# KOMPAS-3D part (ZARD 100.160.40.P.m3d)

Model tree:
1. Операция без истории:1
2. Операция без истории:2
3. Операция без истории:3
4. Операция без истории:4
5. Операция без истории:5
6. Операция без истории:6
7. Операция без истории:7
8. Операция без истории:8
9. Операция без истории:9
10. Операция без истории:10
11. Операция без истории:11
12. Операция без истории:12
13. Операция без истории:13
14. Операция без истории:14
15. Операция без истории:15
16. Операция без истории:16
17. Операция без истории:17
18. Операция без истории:18
19. Операция без истории:19
20. Операция без истории:20
21. Операция без истории:21
22. Операция без истории:22
23. Операция без истории:23
24. Операция без истории:24
25. Операция без истории:25
26. Операция без истории:26
27. Операция без истории:27
28. Операция без истории:28
29. Операция без истории:29
30. Операция без истории:30
31. Операция без истории:31
32. Операция без истории:32
33. Операция без истории:33
34. Операция без истории:34
35. Операция без истории:35
36. Операция без истории:36
37. Операция без истории:37
38. Операция без истории:38
39. Операция без истории:39
40. Операция без истории:40
41. Операция без истории:41
42. Операция без истории:42
43. Операция без истории:43
44. Операция без истории:44
45. Операция без истории:45
46. Операция без истории:46
47. Операция без истории:47
48. Операция без истории:48
49. Операция без истории:49
50. Операция без истории:50
51. Операция без истории:51
52. Операция без истории:52
53. Операция без истории:53
54. Операция без истории:54
55. Операция без истории:55
56. Операция без истории:56
57. Операция без истории:57
58. Операция без истории:58
59. Операция без истории:59
60. Операция без истории:60
61. Операция без истории:61
62. Операция без истории:62
63. Операция без истории:63
64. Операция без истории:64
65. Операция без истории:65
66. Операция без истории:66
67. Операция без истории:67
68. Операция без истории:68
69. Операция без истории:69
70. Операция без истории:70
71. Операция без истории:71
72. Операция без истории:72
73. Операция без истории:73
74. Операция без истории:74
75. Операция без истории:75
76. Операция без истории:76
77. Операция без истории:77
78. Операция без истории:78
79. Операция без истории:79
80. Операция без истории:80
81. Операция без истории:81
82. Операция без истории:82
83. Операция без истории:83
84. Операция без истории:84
85. Операция без истории:85
86. Поверхность без истории:1
87. Поверхность без истории:2
88. Поверхность без истории:3
89. Поверхность без истории:4
90. Поверхность без истории:5
91. Поверхность без истории:6
92. Поверхность без истории:7
93. Поверхность без истории:8

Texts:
  ЗАРД 100.160.40-ХХ.Р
